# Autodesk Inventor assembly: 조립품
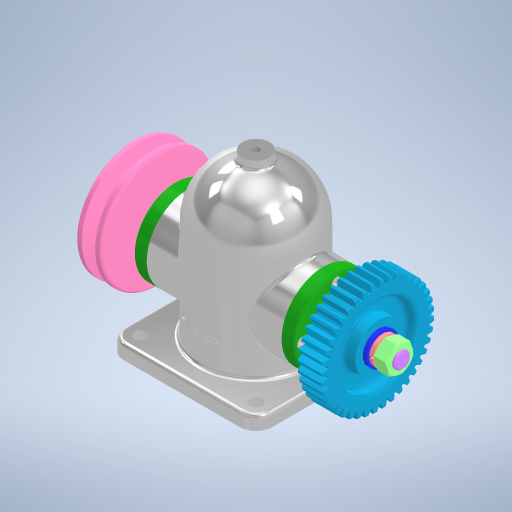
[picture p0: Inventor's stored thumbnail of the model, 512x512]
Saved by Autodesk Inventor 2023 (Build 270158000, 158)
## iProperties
Created: 2025-04
Part Number: 조립품
Document SubType Name: Assembly
Designer: user
Author: user
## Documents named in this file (14)
- C:\Users\user\Desktop\750406V1014\조립품.iam
- C:\Users\user\Desktop\750406V1014\본체.ipt
- C:\Users\user\Desktop\750406V1014\커버.ipt
- C:\Users\user\Desktop\750406V1014\깊은 홈 볼 베어링 6203.ipt
- C:\Users\user\Desktop\750406V1014\축.ipt
- C:\Users\user\Desktop\750406V1014\오일 실 26 38 8.ipt
- C:\Users\user\Desktop\750406V1014\6각 구멍붙이 볼트 M4x12.ipt
- C:\Users\user\Desktop\750406V1014\칼라.ipt
- C:\Users\user\Desktop\750406V1014\평행 키 5x5x12.ipt
- C:\Users\user\Desktop\750406V1014\스퍼기어.ipt
- C:\Users\user\Desktop\750406V1014\V 벨트 풀리.ipt
- C:\Users\user\Desktop\750406V1014\평와셔 M12.ipt
- C:\Users\user\Desktop\750406V1014\스프링 와셔 M12.ipt
- C:\Users\user\Desktop\750406V1014\6각 너트 M12x1.ipt
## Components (11 placed, 3 different names)
1. 6각 구멍붙이 볼트 M4x12:1
2. 6각 구멍붙이 볼트 M4x12:2
3. 6각 구멍붙이 볼트 M4x12:3
4. 6각 구멍붙이 볼트 M4x12:4
5. 6각 구멍붙이 볼트 M4x12:5
6. 6각 구멍붙이 볼트 M4x12:6
7. 6각 구멍붙이 볼트 M4x12:7
8. 6각 구멍붙이 볼트 M4x12:8
9. V 벨트 풀리:1
10. 6각 너트 M12x1:1
11. 6각 너트 M12x1:2
